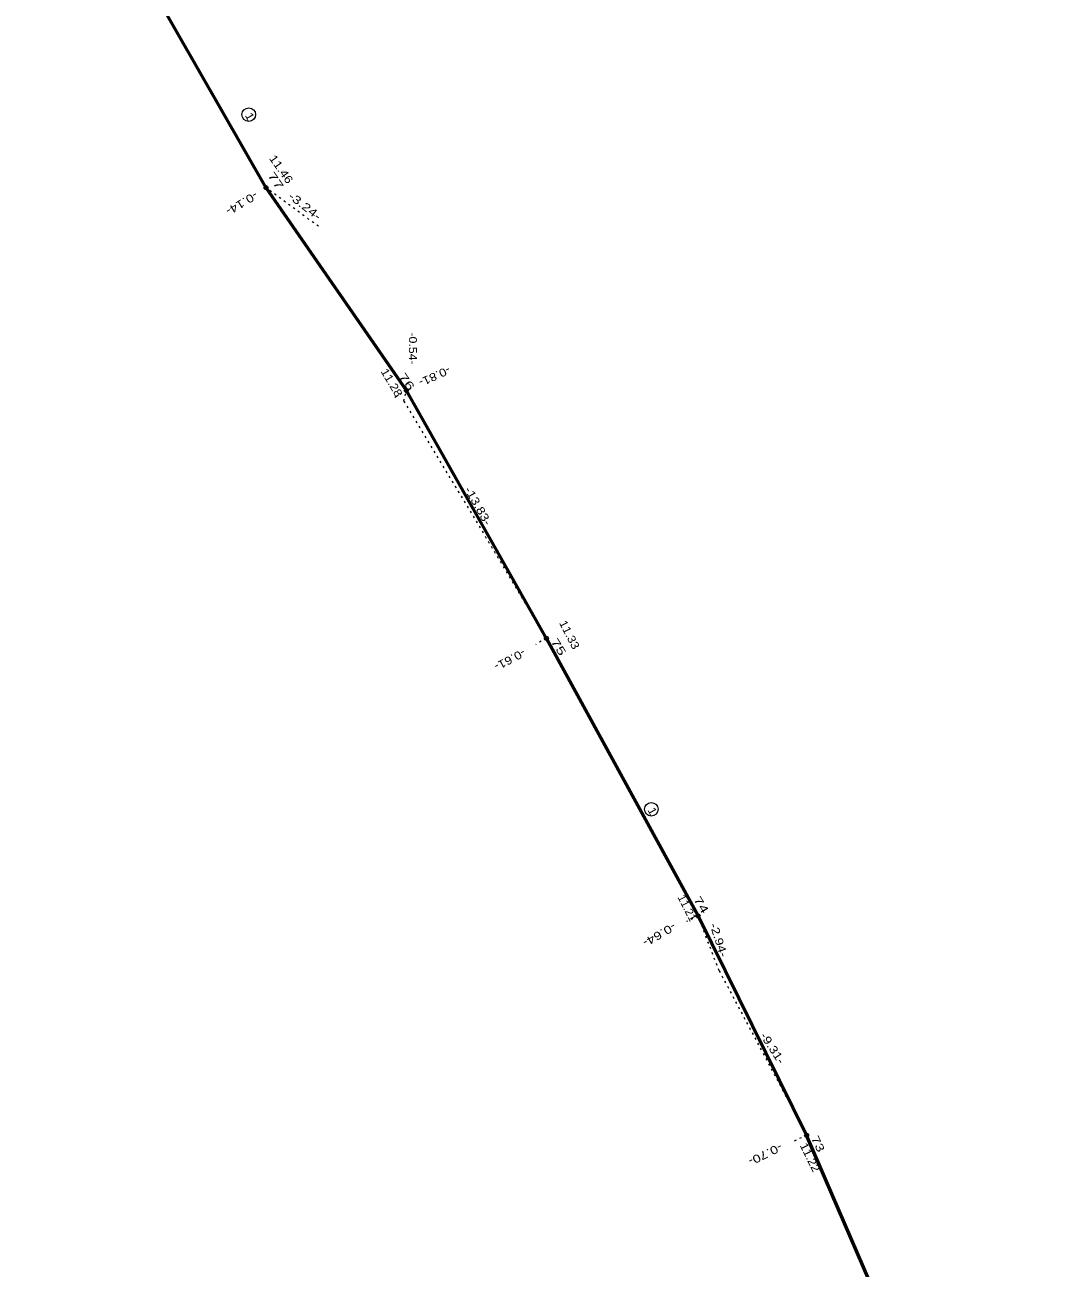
# Model space of a CAD drawing. Extents: x -603113 to -602961, y -1157278 to -1156712.
# Drawn here: x -603059.4 to -603008.1, y -1156849.8 to -1156787.6 of the extents above; entities that cross this region are included whole.
import ezdxf
from ezdxf.enums import TextEntityAlignment as Align

# ---------------------------------------------------------------- set-up
doc = ezdxf.new("R2010")
doc.units = 0
doc.header["$LTSCALE"] = 0.16
doc.header["$PDMODE"] = 32
doc.header["$PDSIZE"] = 0.08
doc.linetypes.add('DOTTED', pattern=[1.5, 0.3, -1.2])
for name, color, linetype, lineweight in [('12', 7, 'Continuous', 53), ('14', 7, 'DOTTED', 13), ('15', 7, 'Continuous', 13)]:
    doc.layers.add(name, color=color, linetype=linetype, lineweight=lineweight)
doc.layers.add('35', color=7, linetype='Continuous')

msp = doc.modelspace()

# ---------------------------------------------------------------- linework, layer by layer
at = {"layer": '12'}
msp.add_lwpolyline([(-603008.05, -1156862.95), (-603013.08, -1156859.75), (-603014.31, -1156857.03), (-603020.32, -1156843.12), (-603025.746, -1156832.154), (-603033.325, -1156818.288), (-603040.317, -1156805.906), (-603047.333, -1156795.776), (-603054.033, -1156784.062), (-603059.389, -1156775.282)], dxfattribs=at)
at = {"layer": '14'}
for p, q in [((-603047.333, -1156795.776), (-603047.452, -1156795.85)), ((-603044.72, -1156797.7), (-603047.333, -1156795.776)), ((-603040.317, -1156805.906), (-603041.012, -1156806.326)), ((-603040.45, -1156806.43), (-603040.317, -1156805.906)), ((-603040.45, -1156806.43), (-603033.325, -1156818.288)), ((-603033.325, -1156818.288), (-603033.858, -1156818.591)), ((-603025.746, -1156832.154), (-603026.318, -1156832.437)), ((-603024.69, -1156834.9), (-603025.746, -1156832.154)), ((-603024.69, -1156834.9), (-603020.32, -1156843.12)), ((-603020.32, -1156843.12), (-603020.954, -1156843.413))]:
    msp.add_line(p, q, dxfattribs=at)
at = {"layer": '15'}
for centre, radius in [((-603048.2019, -1156792.1195), 0.3414), ((-603047.333, -1156795.776), 0.1), ((-603040.317, -1156805.906), 0.1), ((-603033.325, -1156818.288), 0.1), ((-603028.0819, -1156826.8295), 0.3414), ((-603025.746, -1156832.154), 0.1), ((-603020.32, -1156843.12), 0.1)]:
    msp.add_circle(centre, radius, dxfattribs=at)
for p in [(-603047.333, -1156795.776), (-603040.317, -1156805.906), (-603033.325, -1156818.288), (-603025.746, -1156832.154), (-603020.32, -1156843.12)]:
    msp.add_point(p, dxfattribs=at)

# ---------------------------------------------------------------- texts
at = {"layer": '14'}
for s, rotation, width, p in [('-0.14-', 211.258, 1.25, (-603047.901, -1156795.927)), ('-3.24-', 322.242, 1.35, (-603046.264, -1156796.266)), ('-0.54-', 270, 1.15, (-603040.195, -1156803.002)), ('-0.81-', 204.842, 1.2, (-603038.231, -1156804.661)), ('-13.83-', 299.601, 1.25, (-603037.433, -1156810.847)), ('-0.61-', 208.072, 1.2, (-603034.499, -1156818.782)), ('-0.64-', 210.387, 1.3, (-603026.996, -1156832.464)), ('-2.94-', 287.958, 1.25, (-603025.169, -1156832.589)), ('-9.31-', 303.036, 1.25, (-603022.661, -1156838.138)), ('-0.70-', 206.197, 1.3, (-603021.654, -1156843.49))]:
    msp.add_text(s, height=0.4, rotation=rotation, dxfattribs=dict(at, width=width)).set_placement(p)
at = {"layer": '15'}
for s, rotation, width, p in [('1', 298.676, 1.15, (-603048.403, -1156792.152)), ('77', 304.585, 1.55, (-603047.28, -1156795.154)), ('76', 304.51, 1.55, (-603040.731, -1156805.194)), ('75', 301.838, 1.5, (-603033.122, -1156818.443)), ('1', 298.676, 1.15, (-603028.283, -1156826.862)), ('74', 301.47, 1.5, (-603025.993, -1156831.326)), ('73', 295.701, 1.4, (-603020.115, -1156843.257))]:
    msp.add_text(s, height=0.4, rotation=rotation, dxfattribs=dict(at, width=width)).set_placement(p)
at = {"layer": '35'}
for s, rotation, width, p in [('11.46', 305.106, 1.2, (-603046.7419, -1156794.9585)), ('11.28', 300.598, 1.15, (-603041.2281, -1156805.6107)), ('11.33', 297.095, 1.15, (-603032.351, -1156818.1969)), ('11.21', 296.998, 1.05, (-603026.4633, -1156831.8462)), ('11.22', 296.021, 1.15, (-603020.3344, -1156844.3088))]:
    msp.add_text(s, height=0.4, rotation=rotation, dxfattribs=dict(at, width=width)).set_placement(p, align=Align.CENTER)

doc.saveas('drawing.dxf')
